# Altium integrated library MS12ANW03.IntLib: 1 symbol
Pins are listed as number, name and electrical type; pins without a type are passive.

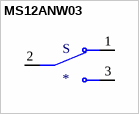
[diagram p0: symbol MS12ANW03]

## MS12ANW03
designator S
Slide Switch SPDT Through Hole; MF: NKK Switches; MP: MS12ANW03
footprint SW_MS12ANW03
pins: 1, 2, 3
